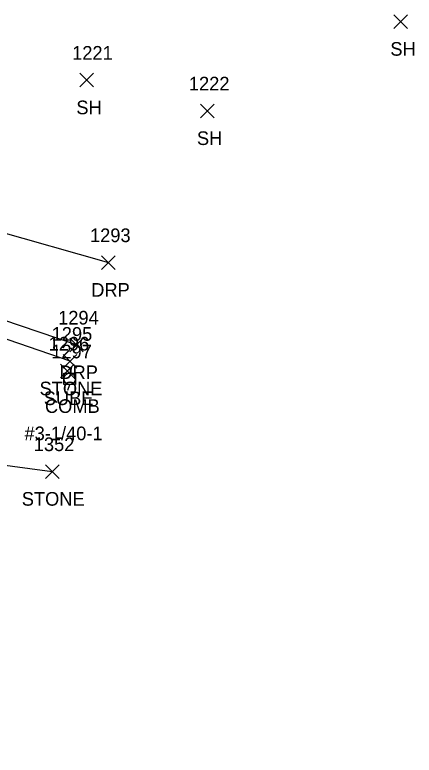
# Model space of a CAD drawing. Extents: x 1599840 to 1601211, y 518904 to 521989.
# Drawn here: x 1600924.1 to 1600982.7, y 521199.4 to 521307.9 of the extents above; entities that cross this region are included whole.
import ezdxf

# ---------------------------------------------------------------- set-up
doc = ezdxf.new("R2010")
doc.units = 0
for name, color, linetype in [('L_A', 7, 'Continuous'), ('L_I', 7, 'Continuous'), ('L_TIC', 7, 'Continuous'), ('LASF', 7, 'Continuous'), ('R_A', 7, 'Continuous'), ('R_I', 7, 'Continuous'), ('R_TIC', 7, 'Continuous'), ('RDP', 7, 'Continuous'), ('U_A', 7, 'Continuous'), ('U_C', 7, 'Continuous'), ('U_I', 7, 'Continuous'), ('U_TIC', 7, 'Continuous'), ('UP', 7, 'Continuous')]:
    doc.layers.add(name, color=color, linetype=linetype)

msp = doc.modelspace()

# ---------------------------------------------------------------- linework, layer by layer
at = {"layer": 'L_TIC'}
for points in [[(1600979.68, 521305.95), (1600981.68, 521307.95)], [(1600981.68, 521305.95), (1600979.68, 521307.95)], [(1600933.67, 521297.37), (1600935.67, 521299.37)], [(1600935.67, 521297.37), (1600933.67, 521299.37)], [(1600951.34, 521292.86), (1600953.34, 521294.86)], [(1600953.34, 521292.86), (1600951.34, 521294.86)], [(1600931.23, 521256.16), (1600933.23, 521258.16)], [(1600933.23, 521256.16), (1600931.23, 521258.16)], [(1600928.62, 521239.98), (1600930.62, 521241.98)], [(1600930.62, 521239.98), (1600928.62, 521241.98)]]:
    msp.add_lwpolyline(points, dxfattribs=at)
at = {"layer": 'LASF'}
for points in [[(1600932.23, 521257.16), (1600915.62, 521262.89), (1600899.79, 521268.65), (1600890.66, 521270.22), (1600882.21, 521270.74), (1600879.38, 521270.38), (1600878.61, 521270.29), (1600872.33, 521268.43), (1600866.31, 521265.35), (1600861.17, 521261.6), (1600854.34, 521254.11), (1600847.55, 521244.88), (1600837.63, 521229.78), (1600834.27, 521222.99), (1600831.35, 521213.17), (1600836.3, 521210.92), (1600841.32, 521208.1), (1600849.91, 521199.4)], [(1600867.09, 521214.92), (1600865.86, 521225.8), (1600878.08, 521242.45), (1600888.16, 521246.58), (1600929.62, 521240.98)]]:
    msp.add_lwpolyline(points, dxfattribs=at)
at = {"layer": 'R_TIC'}
for points in [[(1600936.85, 521270.62), (1600938.85, 521272.62)], [(1600938.85, 521270.62), (1600936.85, 521272.62)], [(1600932.18, 521258.54), (1600934.18, 521260.54)], [(1600934.18, 521258.54), (1600932.18, 521260.54)]]:
    msp.add_lwpolyline(points, dxfattribs=at)
at = {"layer": 'RDP'}
for points in [[(1600874.78, 521305.59), (1600877.36, 521296.17), (1600889.58, 521289.84), (1600907.97, 521281.86), (1600920.96, 521276.4), (1600937.85, 521271.62)], [(1600933.18, 521259.54), (1600916.89, 521265.1), (1600900.66, 521270.53), (1600891.29, 521272.36), (1600882.54, 521272.41), (1600878.89, 521272), (1600871.67, 521270.3), (1600865.92, 521267.55), (1600860.05, 521263.1), (1600858.33, 521264.45), (1600855.45, 521265.34), (1600851.3, 521265.61)]]:
    msp.add_lwpolyline(points, dxfattribs=at)
at = {"layer": 'U_TIC'}
for points in [[(1600930.85, 521254.73), (1600932.85, 521256.73)], [(1600932.85, 521254.73), (1600930.85, 521256.73)]]:
    msp.add_lwpolyline(points, dxfattribs=at)
at = {"layer": 'UP'}
for p, q in [((1600932.43, 521256.24), (1600932.18, 521255.41)), ((1600931.34, 521253.74), (1600931.34, 521255.41)), ((1600931.34, 521255.41), (1600933.01, 521255.41)), ((1600933.01, 521255.41), (1600933.01, 521253.74)), ((1600932.18, 521254.58), (1600932.18, 521254.58)), ((1600933.01, 521253.74), (1600931.34, 521253.74)), ((1600931.93, 521252.91), (1600932.18, 521253.74))]:
    msp.add_line(p, q, dxfattribs=at)
msp.add_circle((1600932.18, 521254.58), 0.833, dxfattribs=at)

# ---------------------------------------------------------------- texts
at = {"layer": 'L_A'}
for s, p in [('SH', (1600979.17, 521301.95)), ('SH', (1600933.16, 521293.37)), ('SH', (1600950.83, 521288.86)), ('STONE', (1600927.77, 521252.16)), ('STONE', (1600925.16, 521235.98))]:
    msp.add_text(s, height=2, dxfattribs=at).set_placement(p)
at = {"layer": 'L_I'}
for s, p in [('1221', (1600932.54, 521301.37)), ('1222', (1600949.65, 521296.86)), ('1295', (1600929.54, 521260.16)), ('1352', (1600926.92, 521243.98))]:
    msp.add_text(s, height=2, dxfattribs=at).set_placement(p)
at = {"layer": 'R_A'}
for p in [(1600935.34, 521266.62), (1600930.67, 521254.54)]:
    msp.add_text('DRP', height=2, dxfattribs=at).set_placement(p)
at = {"layer": 'R_I'}
for s, p in [('1293', (1600935.16, 521274.62)), ('1294', (1600930.49, 521262.54))]:
    msp.add_text(s, height=2, dxfattribs=at).set_placement(p)
at = {"layer": 'U_A'}
for s, p in [('SUBE', (1600928.38, 521250.73)), ('COMB', (1600928.56, 521249.58))]:
    msp.add_text(s, height=2, dxfattribs=at).set_placement(p)
at = {"layer": 'U_C'}
msp.add_text('#3-1/40-1', height=2, dxfattribs=at).set_placement((1600925.56, 521245.58))
at = {"layer": 'U_I'}
for s, p in [('1296', (1600929.1, 521258.73)), ('1297', (1600929.48, 521257.58))]:
    msp.add_text(s, height=2, dxfattribs=at).set_placement(p)

doc.saveas('drawing.dxf')
